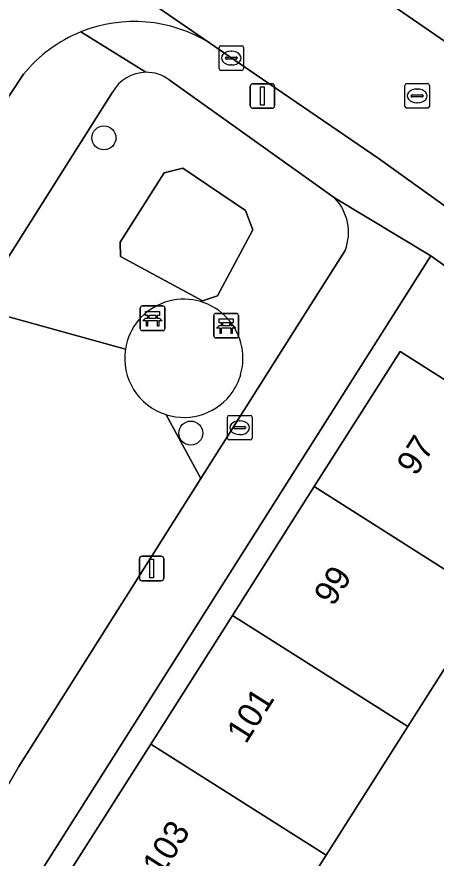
# Model space of a CAD drawing. Extents: x 159039 to 160102, y 381214 to 382524.
# Drawn here: x 159368.3 to 159385.36, y 381848.96 to 381883.21 of the extents above; entities that cross this region are included whole.
import ezdxf

# ---------------------------------------------------------------- set-up
doc = ezdxf.new("R2010")
doc.units = 0
for name, color, linetype in [('IMGEO_Bank', 7, 'Continuous'), ('IMGEO_Boom', 7, 'Continuous'), ('IMGEO_Erf', 7, 'Continuous'), ('IMGEO_Groenvoorziening', 7, 'Continuous'), ('IMGEO_Kolk', 7, 'Continuous'), ('IMGEO_Lichtmast', 7, 'Continuous'), ('IMGEO_Pand', 7, 'Continuous'), ('IMGEO_Pand_nummerreeks', 7, 'Continuous'), ('IMGEO_Rijbaan_lokaal_open', 7, 'Continuous'), ('IMGEO_Rioolput', 7, 'Continuous'), ('IMGEO_Voetpad_halfverhard', 7, 'Continuous'), ('IMGEO_Voetpad_open', 7, 'Continuous')]:
    doc.layers.add(name, color=color, linetype=linetype)

msp = doc.modelspace()

# ---------------------------------------------------------------- linework, layer by layer
at = {"layer": 'IMGEO_Bank'}
for p, q in [((159373.403, 381871.435), (159374.244, 381871.435)), ((159374.244, 381871.435), (159373.403, 381871.435)), ((159373.328, 381870.51), (159373.328, 381871.351)), ((159373.328, 381871.351), (159373.328, 381870.51)), ((159373.637, 381870.941), (159373.637, 381871.047)), ((159373.681, 381871.047), (159373.681, 381870.941)), ((159373.969, 381871.053), (159373.687, 381871.053)), ((159373.975, 381870.941), (159373.975, 381871.047)), ((159374.019, 381871.047), (159374.019, 381870.941)), ((159374.328, 381871.36), (159374.328, 381870.519)), ((159374.328, 381870.519), (159374.328, 381871.36)), ((159376.32, 381870.209), (159376.32, 381871.05)), ((159376.32, 381871.05), (159376.32, 381870.209)), ((159376.395, 381871.134), (159377.236, 381871.134)), ((159377.236, 381871.134), (159376.395, 381871.134)), ((159377.32, 381871.059), (159377.32, 381870.218)), ((159377.32, 381870.218), (159377.32, 381871.059)), ((159374.025, 381870.833), (159373.632, 381870.833)), ((159373.687, 381870.935), (159373.969, 381870.935)), ((159376.629, 381870.64), (159376.629, 381870.746)), ((159376.673, 381870.746), (159376.673, 381870.64)), ((159376.961, 381870.752), (159376.679, 381870.752)), ((159376.967, 381870.64), (159376.967, 381870.746)), ((159377.011, 381870.746), (159377.011, 381870.64)), ((159374.253, 381870.435), (159373.412, 381870.435)), ((159373.412, 381870.435), (159374.253, 381870.435)), ((159377.017, 381870.532), (159376.624, 381870.532)), ((159376.679, 381870.634), (159376.961, 381870.634)), ((159377.245, 381870.134), (159376.404, 381870.134)), ((159376.404, 381870.134), (159377.245, 381870.134))]:
    msp.add_line(p, q, dxfattribs=at)
for points in [[(159373.631, 381871.053), (159373.545, 381871.053), (159373.545, 381871.214), (159374.108, 381871.214), (159374.108, 381871.053), (159374.025, 381871.053)], [(159373.575, 381870.833), (159373.433, 381870.833), (159373.545, 381870.935), (159373.631, 381870.935)], [(159373.625, 381870.826), (159373.625, 381870.619), (159373.582, 381870.619), (159373.582, 381870.826)], [(159374.025, 381870.935), (159374.108, 381870.935), (159374.22, 381870.833), (159374.081, 381870.833)], [(159374.075, 381870.826), (159374.075, 381870.619), (159374.031, 381870.619), (159374.031, 381870.826)], [(159376.623, 381870.752), (159376.537, 381870.752), (159376.537, 381870.913), (159377.1, 381870.913), (159377.1, 381870.752), (159377.017, 381870.752)], [(159376.567, 381870.532), (159376.425, 381870.532), (159376.537, 381870.634), (159376.623, 381870.634)], [(159376.617, 381870.525), (159376.617, 381870.318), (159376.574, 381870.318), (159376.574, 381870.525)], [(159377.017, 381870.634), (159377.1, 381870.634), (159377.212, 381870.532), (159377.073, 381870.532)], [(159377.067, 381870.525), (159377.067, 381870.318), (159377.023, 381870.318), (159377.023, 381870.525)]]:
    msp.add_lwpolyline(points, dxfattribs=at)
for centre, radius, start, end in [((159373.406, 381871.357), 0.0779, 92.4484, 184.2845), ((159373.406, 381871.357), 0.0779, 92.4484, 184.2845), ((159374.25, 381871.357), 0.0779, 2.4484, 94.2845), ((159374.25, 381871.357), 0.0779, 2.4484, 94.2845), ((159373.63, 381871.046), 0.00671, 2.8957, 87.1043), ((159373.687, 381871.046), 0.00671, 92.8957, 177.1043), ((159373.969, 381871.046), 0.00671, 2.8957, 87.1043), ((159374.026, 381871.046), 0.00671, 92.8957, 177.1043), ((159376.398, 381871.056), 0.0779, 92.4484, 184.2845), ((159376.398, 381871.056), 0.0779, 92.4484, 184.2845), ((159377.242, 381871.056), 0.0779, 2.4484, 94.2845), ((159377.242, 381871.056), 0.0779, 2.4484, 94.2845), ((159373.575, 381870.826), 0.00671, 2.8957, 87.1043), ((159373.632, 381870.826), 0.00671, 92.8957, 177.1043), ((159373.63, 381870.942), 0.00671, 272.8957, 357.1043), ((159373.687, 381870.942), 0.00671, 182.8957, 267.1043), ((159373.969, 381870.942), 0.00671, 272.8957, 357.1043), ((159374.026, 381870.942), 0.00671, 182.8957, 267.1043), ((159374.024, 381870.826), 0.00671, 2.8957, 87.1043), ((159374.081, 381870.826), 0.00671, 92.8957, 177.1043), ((159376.622, 381870.745), 0.00671, 2.8957, 87.1043), ((159376.679, 381870.745), 0.00671, 92.8957, 177.1043), ((159376.961, 381870.745), 0.00671, 2.8957, 87.1043), ((159377.018, 381870.745), 0.00671, 92.8957, 177.1043), ((159373.406, 381870.513), 0.0779, 182.4484, 274.2845), ((159373.406, 381870.513), 0.0779, 182.4484, 274.2845), ((159374.25, 381870.513), 0.0779, 272.4484, 4.2845), ((159374.25, 381870.513), 0.0779, 272.4484, 4.2845), ((159376.567, 381870.525), 0.00671, 2.8957, 87.1043), ((159376.624, 381870.525), 0.00671, 92.8957, 177.1043), ((159376.622, 381870.641), 0.00671, 272.8957, 357.1043), ((159376.679, 381870.641), 0.00671, 182.8957, 267.1043), ((159376.961, 381870.641), 0.00671, 272.8957, 357.1043), ((159377.018, 381870.641), 0.00671, 182.8957, 267.1043), ((159377.016, 381870.525), 0.00671, 2.8957, 87.1043), ((159377.073, 381870.525), 0.00671, 92.8957, 177.1043), ((159376.398, 381870.212), 0.0779, 182.4484, 274.2845), ((159376.398, 381870.212), 0.0779, 182.4484, 274.2845), ((159377.242, 381870.212), 0.0779, 272.4484, 4.2845), ((159377.242, 381870.212), 0.0779, 272.4484, 4.2845)]:
    msp.add_arc(centre, radius, start, end, dxfattribs=at)
at = {"layer": 'IMGEO_Boom'}
for centre in [(159371.847, 381878.277), (159375.382, 381866.261)]:
    msp.add_circle(centre, 0.489, dxfattribs=at)
at = {"layer": 'IMGEO_Erf'}
for points in [[(159401.551, 381861.756), (159385.148, 381873.477), (159352.77, 381822.367), (159353.599, 381821.842), (159357.08, 381827.327), (159360.473, 381832.674), (159363.729, 381837.804), (159367.14, 381843.178), (159370.464, 381848.417), (159373.755, 381853.601), (159377.079, 381858.84), (159380.405, 381864.08), (159383.895, 381869.579), (159391.026, 381865.053)], [(159387.536, 381859.554), (159384.21, 381854.314), (159380.886, 381849.076), (159377.596, 381843.891), (159374.271, 381838.652), (159370.86, 381833.278), (159369.074, 381830.464), (159371.131, 381829.158), (159369.661, 381826.842), (159367.604, 381828.148), (159365.414, 381824.697), (159367.114, 381823.618), (159365.91, 381821.722), (159364.211, 381822.801), (159360.73, 381817.316)]]:
    msp.add_lwpolyline(points, dxfattribs=at)
at = {"layer": 'IMGEO_Groenvoorziening'}
for points in [[(159381.223, 381875.841), (159374.506, 381880.639)], [(159372.198, 381880.139), (159367.239, 381872.292), (159366.633, 381871.354), (159372.721, 381869.68)], [(159374.378, 381867.01), (159375.795, 381864.415), (159380.556, 381871.945), (159381.665, 381873.699)], [(159372.721, 381869.68), (159366.633, 381871.354), (159358.524, 381858.795), (159358.302, 381858.425), (159361.185, 381856.719), (159362.405, 381856.12)], [(159375.795, 381864.415), (159374.378, 381867.01)], [(159367.724, 381851.534), (159368.38, 381852.687), (159375.795, 381864.415)]]:
    msp.add_lwpolyline(points, dxfattribs=at)
msp.add_lwpolyline([(159377.606, 381875.321), (159377.907, 381874.539), (159376.47, 381871.851), (159375.858, 381871.638), (159372.524, 381873.451), (159372.509, 381874.026), (159374.292, 381876.849), (159375.062, 381877.046)], close=True, dxfattribs=at)
for centre, radius, start, end in [((159373.569, 381879.38), 1.567, 90.5826, 151.0335), ((159373.572, 381879.378), 1.569, 53.4767, 90.7027), ((159379.768, 381874.424), 2.031, 339.0817, 44.2369), ((159375.098, 381869.306), 2.406, 343.9624, 171.055), ((159375.099, 381869.307), 2.407, 171.0811, 252.5663), ((159375.084, 381869.312), 2.422, 326.3517, 343.9141), ((159375.098, 381869.308), 2.408, 252.6019, 326.2518)]:
    msp.add_arc(centre, radius, start, end, dxfattribs=at)
at = {"layer": 'IMGEO_Kolk'}
for p, q in [((159376.606, 381882.026), (159377.458, 381882.026)), ((159376.531, 381881.1), (159376.531, 381881.952)), ((159377.019, 381881.806), (159377.044, 381881.806)), ((159377.532, 381881.952), (159377.532, 381881.1)), ((159376.79, 381881.52), (159376.79, 381881.532)), ((159377.228, 381881.483), (159376.83, 381881.483)), ((159376.833, 381881.569), (159377.231, 381881.569)), ((159377.274, 381881.532), (159377.274, 381881.52)), ((159377.458, 381881.026), (159376.606, 381881.026)), ((159377.042, 381881.246), (159377.017, 381881.246)), ((159376.946, 381866.98), (159377.798, 381866.98)), ((159376.871, 381866.054), (159376.871, 381866.906)), ((159377.359, 381866.76), (159377.384, 381866.76)), ((159377.872, 381866.906), (159377.872, 381866.054)), ((159377.13, 381866.474), (159377.13, 381866.486)), ((159377.568, 381866.437), (159377.17, 381866.437)), ((159377.173, 381866.523), (159377.571, 381866.523)), ((159377.614, 381866.486), (159377.614, 381866.474)), ((159377.798, 381865.98), (159376.946, 381865.98)), ((159377.382, 381866.2), (159377.357, 381866.2))]:
    msp.add_line(p, q, dxfattribs=at)
for points in [[(159376.606, 381882.026), (159377.458, 381882.026)], [(159376.531, 381881.1), (159376.531, 381881.952)], [(159377.532, 381881.952), (159377.532, 381881.1)], [(159377.458, 381881.026), (159376.606, 381881.026)], [(159376.946, 381866.98), (159377.798, 381866.98)], [(159376.871, 381866.054), (159376.871, 381866.906)], [(159377.872, 381866.906), (159377.872, 381866.054)], [(159377.798, 381865.98), (159376.946, 381865.98)]]:
    msp.add_lwpolyline(points, dxfattribs=at)
for centre, radius, start, end in [((159376.608, 381881.95), 0.0765, 91.552, 178.448), ((159376.608, 381881.95), 0.0765, 91.552, 178.448), ((159377.456, 381881.95), 0.0765, 1.552, 88.448), ((159377.456, 381881.95), 0.0765, 1.552, 88.448), ((159376.83, 381881.529), 0.0403, 85.8775, 175.7526), ((159376.827, 381881.519), 0.0366, 178.938, 274.7102), ((159377.231, 381881.526), 0.043, 264.8664, 352.4533), ((159377.235, 381881.531), 0.0386, 1.7309, 96.639), ((159376.608, 381881.102), 0.0765, 181.552, 268.448), ((159376.608, 381881.102), 0.0765, 181.552, 268.448), ((159377.456, 381881.102), 0.0765, 271.552, 358.448), ((159377.456, 381881.102), 0.0765, 271.552, 358.448), ((159376.948, 381866.904), 0.0765, 91.552, 178.448), ((159376.948, 381866.904), 0.0765, 91.552, 178.448), ((159377.796, 381866.904), 0.0765, 1.552, 88.448), ((159377.796, 381866.904), 0.0765, 1.552, 88.448), ((159377.17, 381866.483), 0.0403, 85.8775, 175.7526), ((159377.167, 381866.473), 0.0366, 178.938, 274.7102), ((159377.571, 381866.48), 0.043, 264.8664, 352.4533), ((159377.575, 381866.485), 0.0386, 1.7309, 96.639), ((159376.948, 381866.056), 0.0765, 181.552, 268.448), ((159376.948, 381866.056), 0.0765, 181.552, 268.448), ((159377.796, 381866.056), 0.0765, 271.552, 358.448), ((159377.796, 381866.056), 0.0765, 271.552, 358.448)]:
    msp.add_arc(centre, radius, start, end, dxfattribs=at)
for centre, major_axis, ratio, start_param, end_param in [((159377.018, 381881.526), (-0.387, 0.002), 0.722429, 4.712389, 7.853982), ((159377.043, 381881.526), (-0.39, 0.002), 0.717154, 1.570796, 4.712389), ((159377.358, 381866.48), (-0.387, 0.002), 0.722429, 4.712389, 7.853982), ((159377.383, 381866.48), (-0.39, 0.002), 0.717154, 1.570796, 4.712389)]:
    msp.add_ellipse(centre, major_axis=major_axis, ratio=ratio, start_param=start_param, end_param=end_param, dxfattribs=at)
at = {"layer": 'IMGEO_Lichtmast'}
for p, q in [((159377.803, 381879.581), (159377.803, 381880.381)), ((159377.803, 381880.381), (159377.803, 381879.581)), ((159377.903, 381880.481), (159378.693, 381880.481)), ((159378.693, 381880.481), (159377.903, 381880.481)), ((159378.793, 381880.381), (159378.793, 381879.581)), ((159378.793, 381879.581), (159378.793, 381880.381)), ((159378.693, 381879.481), (159377.903, 381879.481)), ((159377.903, 381879.481), (159378.693, 381879.481)), ((159373.292, 381860.35), (159373.292, 381861.15)), ((159373.292, 381861.15), (159373.292, 381860.35)), ((159373.392, 381861.25), (159374.182, 381861.25)), ((159374.182, 381861.25), (159373.392, 381861.25)), ((159374.282, 381861.15), (159374.282, 381860.35)), ((159374.282, 381860.35), (159374.282, 381861.15)), ((159374.182, 381860.25), (159373.392, 381860.25)), ((159373.392, 381860.25), (159374.182, 381860.25))]:
    msp.add_line(p, q, dxfattribs=at)
for points in [[(159378.223, 381880.356), (159378.373, 381880.356), (159378.373, 381879.606), (159378.223, 381879.606), (159378.223, 381880.356)], [(159373.712, 381861.125), (159373.862, 381861.125), (159373.862, 381860.375), (159373.712, 381860.375), (159373.712, 381861.125)]]:
    msp.add_lwpolyline(points, dxfattribs=at)
for centre, start, end in [((159377.903, 381880.381), 90, 180), ((159377.903, 381880.381), 90, 180), ((159378.693, 381880.381), 0, 90), ((159378.693, 381880.381), 360, 90), ((159377.903, 381879.581), 180, 270), ((159377.903, 381879.581), 180, 270), ((159378.693, 381879.581), 270, 0), ((159378.693, 381879.581), 270, 0), ((159373.392, 381861.15), 90, 180), ((159373.392, 381861.15), 90, 180), ((159374.182, 381861.15), 0, 90), ((159374.182, 381861.15), 360, 90), ((159373.392, 381860.35), 180, 270), ((159373.392, 381860.35), 180, 270), ((159374.182, 381860.35), 270, 0), ((159374.182, 381860.35), 270, 0)]:
    msp.add_arc(centre, 0.1, start, end, dxfattribs=at)
at = {"layer": 'IMGEO_Pand'}
for points in [[(159387.536, 381859.554), (159388.347, 381860.832), (159391.026, 381865.053), (159383.895, 381869.579), (159380.405, 381864.08)], [(159377.079, 381858.84), (159384.21, 381854.314), (159387.536, 381859.554), (159380.405, 381864.08)], [(159377.079, 381858.84), (159373.755, 381853.601), (159380.886, 381849.076), (159384.21, 381854.314)], [(159370.464, 381848.417), (159377.596, 381843.891), (159380.886, 381849.076), (159373.755, 381853.601)]]:
    msp.add_lwpolyline(points, close=True, dxfattribs=at)
at = {"layer": 'IMGEO_Rijbaan_lokaal_open'}
for points in [[(159351.831, 381901.396), (159354.473, 381898.459), (159356.724, 381896.513), (159360.469, 381893.231), (159361.778, 381891.943), (159362.316, 381891.65), (159376.136, 381882.142), (159377.184, 381881.424), (159383.005, 381877.455), (159388.94, 381873.188), (159397.966, 381866.975), (159406.023, 381861.421), (159413.89, 381855.955), (159417.059, 381853.43), (159421.598, 381850.302)], [(159376.136, 381882.142), (159362.316, 381891.65)], [(159424.695, 381854.911), (159420.402, 381857.938), (159418.724, 381859.338), (159409.164, 381865.996), (159401.266, 381871.522), (159394.639, 381876.061), (159382.491, 381884.442), (159378.766, 381887.027), (159378.123, 381887.473), (159374.914, 381889.793), (159372.607, 381891.419)], [(159331.013, 381821.972), (159336.748, 381830.974), (159337.644, 381832.292), (159338.189, 381833.159), (159342.307, 381839.702), (159347.915, 381848.544), (159353.758, 381857.696), (159361.37, 381869.614), (159365.312, 381875.921), (159366.451, 381877.655), (159367.537, 381879.308), (159368.58, 381880.87)]]:
    msp.add_lwpolyline(points, dxfattribs=at)
for centre, radius, start, end in [((159373.079, 381877.215), 5.799, 58.1849, 111.9995), ((159373.089, 381877.206), 5.81, 112.0631, 140.9086)]:
    msp.add_arc(centre, radius, start, end, dxfattribs=at)
at = {"layer": 'IMGEO_Rioolput'}
for p, q in [((159384.091, 381879.561), (159384.091, 381880.413)), ((159384.166, 381880.487), (159385.018, 381880.487)), ((159384.579, 381880.267), (159384.604, 381880.267)), ((159385.092, 381880.413), (159385.092, 381879.561)), ((159384.35, 381879.981), (159384.35, 381879.993)), ((159384.788, 381879.944), (159384.39, 381879.944)), ((159384.393, 381880.03), (159384.791, 381880.03)), ((159384.834, 381879.993), (159384.834, 381879.981)), ((159384.602, 381879.707), (159384.577, 381879.707)), ((159385.018, 381879.487), (159384.166, 381879.487))]:
    msp.add_line(p, q, dxfattribs=at)
for points in [[(159384.091, 381879.561), (159384.091, 381880.413)], [(159384.166, 381880.487), (159385.018, 381880.487)], [(159385.092, 381880.413), (159385.092, 381879.561)], [(159385.018, 381879.487), (159384.166, 381879.487)]]:
    msp.add_lwpolyline(points, dxfattribs=at)
for centre, radius, start, end in [((159384.168, 381880.411), 0.0765, 91.552, 178.448), ((159384.168, 381880.411), 0.0765, 91.552, 178.448), ((159385.016, 381880.411), 0.0765, 1.552, 88.448), ((159385.016, 381880.411), 0.0765, 1.552, 88.448), ((159384.39, 381879.99), 0.0403, 85.8775, 175.7526), ((159384.387, 381879.98), 0.0366, 178.938, 274.7102), ((159384.791, 381879.987), 0.043, 264.8664, 352.4533), ((159384.795, 381879.992), 0.0386, 1.7309, 96.639), ((159384.168, 381879.563), 0.0765, 181.552, 268.448), ((159384.168, 381879.563), 0.0765, 181.552, 268.448), ((159385.016, 381879.563), 0.0765, 271.552, 358.448), ((159385.016, 381879.563), 0.0765, 271.552, 358.448)]:
    msp.add_arc(centre, radius, start, end, dxfattribs=at)
for centre, major_axis, ratio, start_param, end_param in [((159384.578, 381879.987), (-0.387, 0.002), 0.722429, 4.712389, 7.853982), ((159384.603, 381879.987), (-0.39, 0.002), 0.717154, 1.570796, 4.712389)]:
    msp.add_ellipse(centre, major_axis=major_axis, ratio=ratio, start_param=start_param, end_param=end_param, dxfattribs=at)
at = {"layer": 'IMGEO_Voetpad_halfverhard'}
msp.add_lwpolyline([(159372.524, 381873.451), (159375.858, 381871.638), (159376.47, 381871.851), (159377.907, 381874.539), (159377.606, 381875.321), (159375.062, 381877.046), (159374.292, 381876.849), (159372.509, 381874.026)], close=True, dxfattribs=at)
for centre, radius, start, end in [((159375.098, 381869.306), 2.406, 343.9624, 171.055), ((159375.099, 381869.307), 2.407, 171.0811, 252.5663), ((159375.084, 381869.312), 2.422, 326.3517, 343.9141), ((159375.098, 381869.308), 2.408, 252.6019, 326.2518)]:
    msp.add_arc(centre, radius, start, end, dxfattribs=at)
at = {"layer": 'IMGEO_Voetpad_open'}
for points in [[(159356.898, 381904.755), (159359.228, 381902.824), (159361.803, 381900.713), (159364.908, 381898.01), (159368.906, 381894.441), (159371.682, 381891.995), (159372.607, 381891.419), (159374.914, 381889.793), (159378.123, 381887.473), (159378.766, 381887.027), (159382.491, 381884.442), (159394.639, 381876.061), (159401.266, 381871.522), (159409.164, 381865.996), (159418.724, 381859.338), (159420.402, 381857.938), (159424.695, 381854.911)], [(159373.553, 381880.947), (159370.907, 381882.591)], [(159370.907, 381882.591), (159373.553, 381880.947)], [(159383.005, 381877.455), (159377.184, 381881.424), (159376.136, 381882.142)], [(159368.58, 381880.87), (159367.537, 381879.308), (159366.451, 381877.655)], [(159374.506, 381880.639), (159381.223, 381875.841), (159385.148, 381873.477), (159401.551, 381861.756), (159402.805, 381860.86), (159416.367, 381851.168), (159421.342, 381847.712), (159423.116, 381848.629)], [(159343.419, 381834.788), (159348.023, 381842.053), (159348.816, 381843.306), (159356.8, 381855.922), (159357.599, 381857.253), (159358.302, 381858.425), (159358.524, 381858.795), (159366.633, 381871.354), (159367.239, 381872.292), (159372.198, 381880.139)], [(159421.598, 381850.302), (159417.059, 381853.43), (159413.89, 381855.955), (159406.023, 381861.421), (159397.966, 381866.975), (159388.94, 381873.188), (159383.005, 381877.455)], [(159385.148, 381873.477), (159381.223, 381875.841)], [(159315.336, 381791.878), (159316.513, 381793.622), (159318.701, 381796.901), (159323.053, 381803.757), (159328.169, 381811.846), (159329.103, 381813.324), (159339.22, 381829.322), (159340.106, 381828.76), (159347.007, 381824.38), (159352.041, 381821.217), (159352.77, 381822.367), (159385.148, 381873.477)], [(159381.665, 381873.699), (159380.556, 381871.945), (159375.795, 381864.415), (159368.38, 381852.687), (159367.724, 381851.534), (159367.032, 381850.318), (159366.269, 381848.977), (159358.779, 381837.209), (159354.639, 381830.704), (159354.068, 381829.807), (159353.284, 381828.575)]]:
    msp.add_lwpolyline(points, dxfattribs=at)
for centre, radius, start, end in [((159373.079, 381877.215), 5.799, 58.1849, 111.9995), ((159373.089, 381877.206), 5.81, 112.0631, 140.9086), ((159373.569, 381879.38), 1.567, 90.5826, 151.0335), ((159373.572, 381879.378), 1.569, 53.4767, 90.7027), ((159379.768, 381874.424), 2.031, 339.0817, 44.2369)]:
    msp.add_arc(centre, radius, start, end, dxfattribs=at)

# ---------------------------------------------------------------- texts
at = {"layer": 'IMGEO_Pand_nummerreeks'}
for s, p in [('97', (159384.538, 381864.472)), ('99', (159381.172, 381859.168)), ('101', (159377.621, 381853.571)), ('103', (159374.193, 381848.171))]:
    msp.add_text(s, height=1, rotation=57.599, dxfattribs=at).set_placement(p)

doc.saveas('drawing.dxf')
